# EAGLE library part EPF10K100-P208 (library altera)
EPF10K100 FLEX 10K family
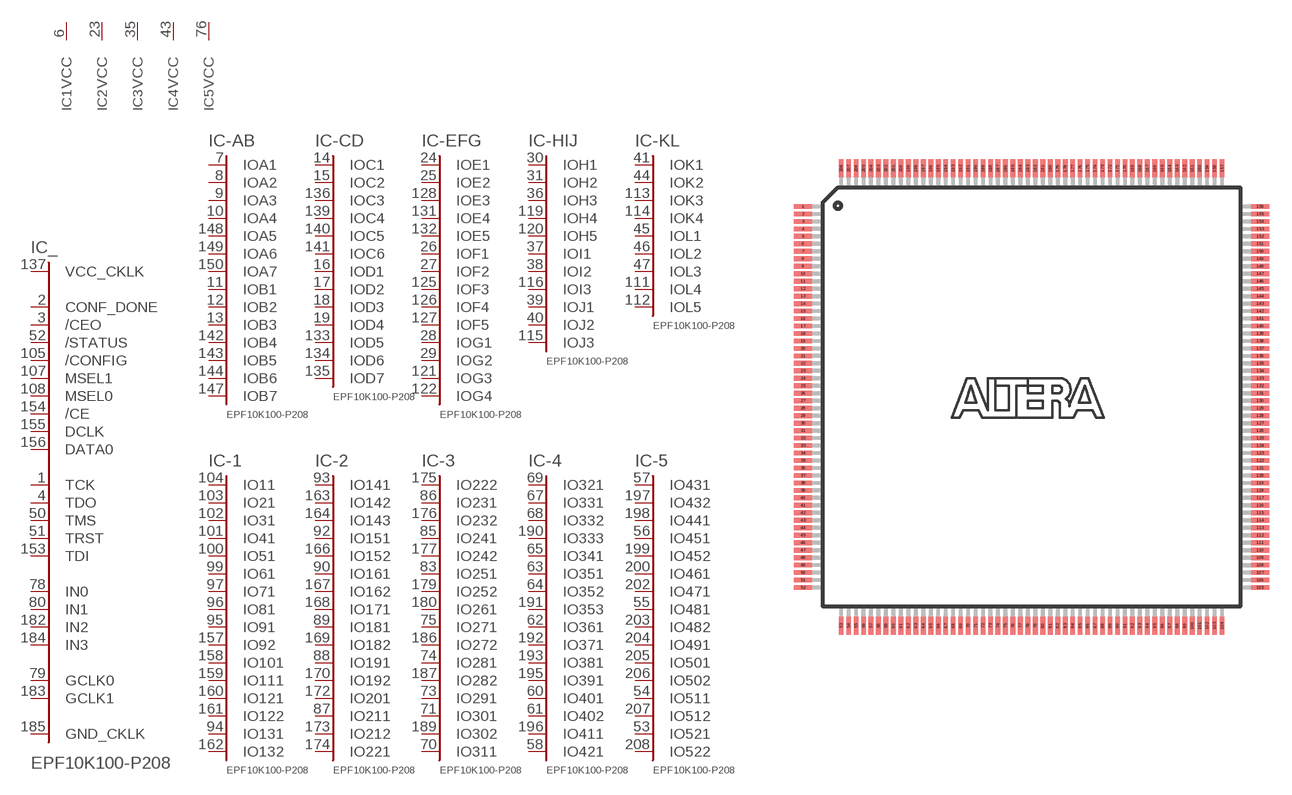
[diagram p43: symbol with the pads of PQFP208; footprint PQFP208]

Designator prefix IC; gates _=100P208C -AB=A7B7 -CD=C6D7 -EFG=E4F4G4 -HIJ=H5I3J3 -KL=K4L5 -1=132-208 -2=221-208 -3=311-208 -4=421-208 -5=522-208 1=VCCINT 2=VCCINT 3=VCCINT 4=VCCINT 5=VCCINT 6=VCCINT 7=VCCINT 8=VCCINT 9=VCCINT 10=VCCINT 11=VCCIO 12=VCCIO 13=VCCIO 14=VCCIO 15=VCCIO 16=VCCIO 17=VCCIO 18=VCCIO 19=VCCIO 20=VCCIO 21=VCCIO 22=VCCIO 23=VCCIO 24=VCCIO 25=GNDINT 26=GNDINT 27=GNDINT 28=GNDINT 29=GNDINT 30=GNDINT 31=GNDINT 32=GNDINT 33=GNDIO 34=GNDIO 35=GNDIO 36=GNDIO 37=GNDIO 38=GNDIO 39=GNDIO 40=GNDIO 41=GNDIO 42=GNDIO 43=GNDIO 44=GNDIO 45=VCCINT

## EPF10K100-P208 (MPN: EPF10K100EQC208-1; OC_FARNELL: unknown; OC_NEWARK: 51R8827)  [PQFP208]
1  _:TCK
2  _:CONF_DONE  in
3  _:/CEO  in
4  _:TDO
5  11:VCCIO  pwr
6  1:VCC  pwr
7  -AB:IOA1
8  -AB:IOA2
9  -AB:IOA3
10  -AB:IOA4
11  -AB:IOB1
12  -AB:IOB2
13  -AB:IOB3
14  -CD:IOC1
15  -CD:IOC2
16  -CD:IOD1
17  -CD:IOD2
18  -CD:IOD3
19  -CD:IOD4
20  33:GNDIO  pwr
21  25:GND  pwr
22  12:VCCIO  pwr
23  2:VCC  pwr
24  -EFG:IOE1
25  -EFG:IOE2
26  -EFG:IOF1
27  -EFG:IOF2
28  -EFG:IOG1
29  -EFG:IOG2
30  -HIJ:IOH1
31  -HIJ:IOH2
32  34:GNDIO  pwr
33  26:GND  pwr
34  13:VCCIO  pwr
35  3:VCC  pwr
36  -HIJ:IOH3
37  -HIJ:IOI1
38  -HIJ:IOI2
39  -HIJ:IOJ1
40  -HIJ:IOJ2
41  -KL:IOK1
42  14:VCCIO  pwr
43  4:VCC  pwr
44  -KL:IOK2
45  -KL:IOL1
46  -KL:IOL2
47  -KL:IOL3
48  35:GNDIO  pwr
49  27:GND  pwr
50  _:TMS
51  _:TRST
52  _:/STATUS  in
53  -5:IO521
54  -5:IO511
55  -5:IO481
56  -5:IO451
57  -5:IO431
58  -4:IO421
59  36:GNDIO  pwr
60  -4:IO401
61  -4:IO402
62  -4:IO361
63  -4:IO351
64  -4:IO352
65  -4:IO341
66  15:VCCIO  pwr
67  -4:IO331
68  -4:IO332
69  -4:IO321
70  -3:IO311
71  -3:IO301
72  37:GNDIO  pwr
73  -3:IO291
74  -3:IO281
75  -3:IO271
76  5:VCC  pwr
77  6:VCC  pwr
78  _:IN0  in
79  _:GCLK0  in
80  _:IN1  in
81  28:GND  pwr
82  29:GND  pwr
83  -3:IO251
84  16:VCCIO  pwr
85  -3:IO241
86  -3:IO231
87  -2:IO211
88  -2:IO191
89  -2:IO181
90  -2:IO161
91  38:GNDIO  pwr
92  -2:IO151
93  -2:IO141
94  -1:IO131
95  -1:IO91
96  -1:IO81
97  -1:IO71
98  17:VCCIO  pwr
99  -1:IO61
100  -1:IO51
101  -1:IO41
102  -1:IO31
103  -1:IO21
104  -1:IO11
105  _:/CONFIG  in
106  7:VCC  pwr
107  _:MSEL1  in
108  _:MSEL0  in
109  8:VCC  pwr
110  18:VCCIO  pwr
111  -KL:IOL4
112  -KL:IOL5
113  -KL:IOK3
114  -KL:IOK4
115  -HIJ:IOJ3
116  -HIJ:IOI3
117  9:VCC  pwr
118  19:VCCIO  pwr
119  -HIJ:IOH4
120  -HIJ:IOH5
121  -EFG:IOG3
122  -EFG:IOG4
123  30:GND  pwr
124  39:GNDIO  pwr
125  -EFG:IOF3
126  -EFG:IOF4
127  -EFG:IOF5
128  -EFG:IOE3
129  31:GND  pwr
130  40:GNDIO  pwr
131  -EFG:IOE4
132  -EFG:IOE5
133  -CD:IOD5
134  -CD:IOD6
135  -CD:IOD7
136  -CD:IOC3
137  _:VCC_CKLK  pas
138  20:VCCIO  pwr
139  -CD:IOC4
140  -CD:IOC5
141  -CD:IOC6
142  -AB:IOB4
143  -AB:IOB5
144  -AB:IOB6
145  10:VCC  pwr
146  21:VCCIO  pwr
147  -AB:IOB7
148  -AB:IOA5
149  -AB:IOA6
150  -AB:IOA7
151  32:GND  pwr
152  41:GNDIO  pwr
153  _:TDI
154  _:/CE  in
155  _:DCLK  in
156  _:DATA0  in
157  -1:IO92
158  -1:IO101
159  -1:IO111
160  -1:IO121
161  -1:IO122
162  -1:IO132
163  -2:IO142
164  -2:IO143
165  22:VCCIO  pwr
166  -2:IO152
167  -2:IO162
168  -2:IO171
169  -2:IO182
170  -2:IO192
171  42:GNDIO  pwr
172  -2:IO201
173  -2:IO212
174  -2:IO221
175  -3:IO222
176  -3:IO232
177  -3:IO242
178  23:VCCIO  pwr
179  -3:IO252
180  -3:IO261
181  45:VCC  pwr
182  _:IN2  in
183  _:GCLK1  in
184  _:IN3  in
185  _:GND_CKLK  pas
186  -3:IO272
187  -3:IO282
188  43:GNDIO  pwr
189  -3:IO302
190  -4:IO333
191  -4:IO353
192  -4:IO371
193  -4:IO381
194  24:VCCIO  pwr
195  -4:IO391
196  -4:IO411
197  -5:IO432
198  -5:IO441
199  -5:IO452
200  -5:IO461
201  44:GNDIO  pwr
202  -5:IO471
203  -5:IO482
204  -5:IO491
205  -5:IO501
206  -5:IO502
207  -5:IO512
208  -5:IO522

## Footprint PQFP208 (pad centres in mm)
Plastic Quad Flat Pack
smd 1.2 x 0.32: 1 -15.3,12.75; 2 -15.3,12.25; 3 -15.3,11.75; 4 -15.3,11.25; 5 -15.3,10.75; 6 -15.3,10.25; 7 -15.3,9.75; 8 -15.3,9.25; 9 -15.3,8.75; 10 -15.3,8.25; 11 -15.3,7.75; 12 -15.3,7.25; 13 -15.3,6.75; 14 -15.3,6.25; 15 -15.3,5.75; 16 -15.3,5.25; 17 -15.3,4.75; 18 -15.3,4.25; 19 -15.3,3.75; 20 -15.3,3.25; 21 -15.3,2.75; 22 -15.3,2.25; 23 -15.3,1.75; 24 -15.3,1.25; 25 -15.3,0.75; 26 -15.3,0.25; 27 -15.3,-0.25; 28 -15.3,-0.75; 29 -15.3,-1.25; 30 -15.3,-1.75; 31 -15.3,-2.25; 32 -15.3,-2.75; 33 -15.3,-3.25; 34 -15.3,-3.75; 35 -15.3,-4.25; 36 -15.3,-4.75; 37 -15.3,-5.25; 38 -15.3,-5.75; 39 -15.3,-6.25; 40 -15.3,-6.75; 41 -15.3,-7.25; 42 -15.3,-7.75; 43 -15.3,-8.25; 44 -15.3,-8.75; 45 -15.3,-9.25; 46 -15.3,-9.75; 47 -15.3,-10.25; 48 -15.3,-10.75; 49 -15.3,-11.25; 50 -15.3,-11.75; 51 -15.3,-12.25; 52 -15.3,-12.75; 105 15.3,-12.75; 106 15.3,-12.25; 107 15.3,-11.75; 108 15.3,-11.25; 109 15.3,-10.75; 110 15.3,-10.25; 111 15.3,-9.75; 112 15.3,-9.25; 113 15.3,-8.75; 114 15.3,-8.25; 115 15.3,-7.75; 116 15.3,-7.25; 117 15.3,-6.75; 118 15.3,-6.25; 119 15.3,-5.75; 120 15.3,-5.25; 121 15.3,-4.75; 122 15.3,-4.25; 123 15.3,-3.75; 124 15.3,-3.25; 125 15.3,-2.75; 126 15.3,-2.25; 127 15.3,-1.75; 128 15.3,-1.25; 129 15.3,-0.75; 130 15.3,-0.25; 131 15.3,0.25; 132 15.3,0.75; 133 15.3,1.25; 134 15.3,1.75; 135 15.3,2.25; 136 15.3,2.75; 137 15.3,3.25; 138 15.3,3.75; 139 15.3,4.25; 140 15.3,4.75; 141 15.3,5.25; 142 15.3,5.75; 143 15.3,6.25; 144 15.3,6.75; 145 15.3,7.25; 146 15.3,7.75; 147 15.3,8.25; 148 15.3,8.75; 149 15.3,9.25; 150 15.3,9.75; 151 15.3,10.25; 152 15.3,10.75; 153 15.3,11.25; 154 15.3,11.75; 155 15.3,12.25; 156 15.3,12.75
smd 0.32 x 1.2: 53 -12.75,-15.3; 54 -12.25,-15.3; 55 -11.75,-15.3; 56 -11.25,-15.3; 57 -10.75,-15.3; 58 -10.25,-15.3; 59 -9.75,-15.3; 60 -9.25,-15.3; 61 -8.75,-15.3; 62 -8.25,-15.3; 63 -7.75,-15.3; 64 -7.25,-15.3; 65 -6.75,-15.3; 66 -6.25,-15.3; 67 -5.75,-15.3; 68 -5.25,-15.3; 69 -4.75,-15.3; 70 -4.25,-15.3; 71 -3.75,-15.3; 72 -3.25,-15.3; 73 -2.75,-15.3; 74 -2.25,-15.3; 75 -1.75,-15.3; 76 -1.25,-15.3; 77 -0.75,-15.3; 78 -0.25,-15.3; 79 0.25,-15.3; 80 0.75,-15.3; 81 1.25,-15.3; 82 1.75,-15.3; 83 2.25,-15.3; 84 2.75,-15.3; 85 3.25,-15.3; 86 3.75,-15.3; 87 4.25,-15.3; 88 4.75,-15.3; 89 5.25,-15.3; 90 5.75,-15.3; 91 6.25,-15.3; 92 6.75,-15.3; 93 7.25,-15.3; 94 7.75,-15.3; 95 8.25,-15.3; 96 8.75,-15.3; 97 9.25,-15.3; 98 9.75,-15.3; 99 10.25,-15.3; 100 10.75,-15.3; 101 11.25,-15.3; 102 11.75,-15.3; 103 12.25,-15.3; 104 12.75,-15.3; 157 12.75,15.3; 158 12.25,15.3; 159 11.75,15.3; 160 11.25,15.3; 161 10.75,15.3; 162 10.25,15.3; 163 9.75,15.3; 164 9.25,15.3; 165 8.75,15.3; 166 8.25,15.3; 167 7.75,15.3; 168 7.25,15.3; 169 6.75,15.3; 170 6.25,15.3; 171 5.75,15.3; 172 5.25,15.3; 173 4.75,15.3; 174 4.25,15.3; 175 3.75,15.3; 176 3.25,15.3; 177 2.75,15.3; 178 2.25,15.3; 179 1.75,15.3; 180 1.25,15.3; 181 0.75,15.3; 182 0.25,15.3; 183 -0.25,15.3; 184 -0.75,15.3; 185 -1.25,15.3; 186 -1.75,15.3; 187 -2.25,15.3; 188 -2.75,15.3; 189 -3.25,15.3; 190 -3.75,15.3; 191 -4.25,15.3; 192 -4.75,15.3; 193 -5.25,15.3; 194 -5.75,15.3; 195 -6.25,15.3; 196 -6.75,15.3; 197 -7.25,15.3; 198 -7.75,15.3; 199 -8.25,15.3; 200 -8.75,15.3; 201 -9.25,15.3; 202 -9.75,15.3; 203 -10.25,15.3; 204 -10.75,15.3; 205 -11.25,15.3; 206 -11.75,15.3; 207 -12.25,15.3; 208 -12.75,15.3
